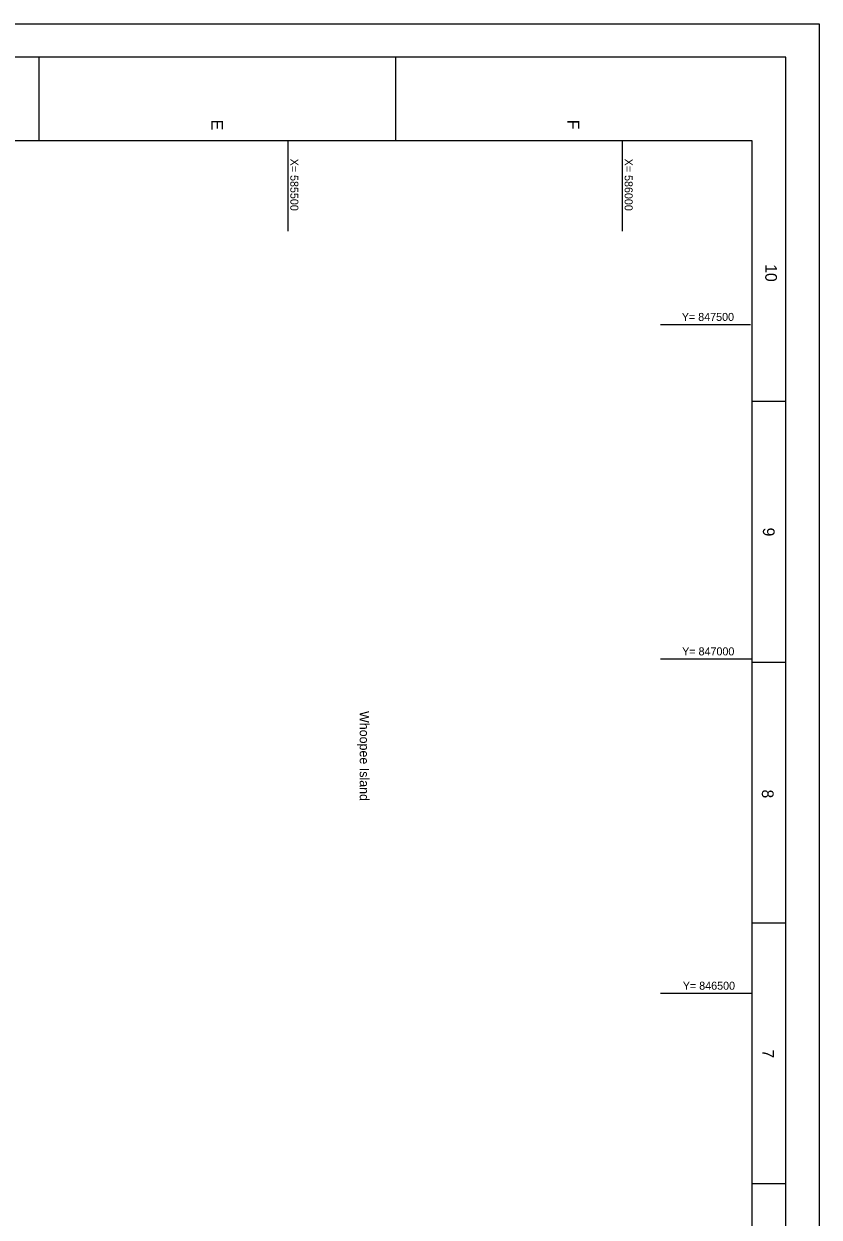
# Model space of a CAD drawing. Extents: x 582894 to 586294, y 843549 to 847949.
# Drawn here: x 585105 to 586294, y 846165 to 847949 of the extents above; entities that cross this region are included whole.
import ezdxf

# ---------------------------------------------------------------- set-up
doc = ezdxf.new("R2010")
doc.units = 0
for name, color, linetype in [('G-ANNO-NPLT', 7, 'Continuous'), ('G-ANNO-TTLB', 7, 'Continuous'), ('V-SITE-IDEN', 7, 'Continuous'), ('V-TOPO-COOR-STAT', 7, 'Continuous')]:
    doc.layers.add(name, color=color, linetype=linetype)

msp = doc.modelspace()

# ---------------------------------------------------------------- linework, layer by layer
at = {"layer": 'G-ANNO-NPLT'}
msp.add_lwpolyline([(586294, 847949.5), (586294, 843549.5), (582894, 843549.5), (582894, 847949.5)], close=True, dxfattribs=at)
msp.add_lwpolyline([(586244, 847949.5), (586294, 847949.5), (586294, 847899.5)], dxfattribs=at)
at = {"layer": 'G-ANNO-TTLB'}
for p, q in [((585127.2, 847899.5), (585127.2, 847774.5)), ((585660.5, 847899.5), (585660.5, 847774.5)), ((586244, 847384.5), (586194, 847384.5)), ((586244, 846994.5), (586194, 846994.5)), ((586244, 846994.5), (586194, 846994.5)), ((586244, 846604.5), (586194, 846604.5)), ((586244, 846214.5), (586194, 846214.5))]:
    msp.add_line(p, q, dxfattribs=at)
for points in [[(582944, 847899.5), (582944, 843599.5), (586244, 843599.5), (586244, 847899.5)], [(586194, 843649.5), (586194, 847774.5), (582994, 847774.5), (582994, 843649.5)]]:
    msp.add_lwpolyline(points, close=True, dxfattribs=at)
at = {"layer": 'V-TOPO-COOR-STAT'}
for p, q in [((585500, 847639.5), (585500, 847774.5)), ((586000, 847639.5), (586000, 847774.5)), ((586056.9, 847500), (586191.1, 847500)), ((586056.9, 847000), (586192.1, 847000)), ((586056.9, 846500), (586194, 846500))]:
    msp.add_line(p, q, dxfattribs=at)

# ---------------------------------------------------------------- texts
at = {"layer": 'G-ANNO-TTLB'}
for s, p in [('E', (585384.9, 847806.1)), ('F', (585917.6, 847805.9)), ('10', (586213.4, 847589.9)), ('9', (586209.9, 847196.1)), ('8', (586208.3, 846804.4)), ('7', (586209, 846415.7))]:
    msp.add_text(s, height=17.5, rotation=270, dxfattribs=at).set_placement(p)
at = {"layer": 'V-SITE-IDEN'}
msp.add_text('Whoopee Island', height=13.92, rotation=270, dxfattribs=at).set_placement((585606.9, 846921.8))
at = {"layer": 'V-TOPO-COOR-STAT'}
for s, p in [('X= 585500', (585503.1, 847747.9)), ('X= 586000', (586003.1, 847747.9))]:
    msp.add_text(s, height=12, rotation=270, dxfattribs=at).set_placement(p)
for s, p in [('Y= 847500', (586088.6, 847505.2)), ('Y= 847000', (586089.1, 847005)), ('Y= 846500', (586090.1, 846505))]:
    msp.add_text(s, height=12, dxfattribs=at).set_placement(p)

doc.saveas('drawing.dxf')
